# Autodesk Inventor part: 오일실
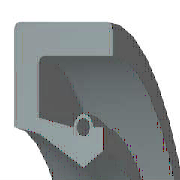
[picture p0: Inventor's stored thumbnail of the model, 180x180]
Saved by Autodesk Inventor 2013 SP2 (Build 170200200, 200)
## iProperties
IsCustomPart: 1
Company: 한국ATC센터
Created: 2014-10
Part Number: 오일실
Material: 고무
Description: 오일-실
Document SubType Name: Modeling
Standard: KS B 2804
Designer: 한국ATC센터
Standards Organization: KS
Language: ko-KR
Size Designation: S - 25 40 8
Categories: <MemberInstance><Categories><Category DisplayName="샤프트 부품" InternalName="7f7aeb1f-a693-4053-b835-cee3144e0d98" Mnemonic="SHFT"><Category DisplayName="실링" Intern
Density: 0.93 g/cm^3
Mass: 2.48215 g
Surface Area: 40.3381 cm^2
Volume: 2.66898 cm^3
Author: KYOUNG IL JANG
Revision Number: 1
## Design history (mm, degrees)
revolve "본체" stored, may be unused: angle "d17" = 90 deg
revolve "스프링1" stored, may be unused: angle "d18" = 90 deg
body "Solid1"
sketch "스케치1"
  geometry: L1 (0, 20)-(8, 20); L2 (8, 20)-(8, 18.75); L3 (8, 18.75)-(1.75, 18.75); L4 (0, 20)-(0, 14.6); L5 (0, 14.6)-(1.75, 14.25); L6 (1.75, 14.25)-(4.9, 12.5); L7 (4.9, 12.5)-(0, 12.5); L8 (6.3, 13.375)-(6.3, 14.6); L9 (0, 0)-(9.586, 0) reference; L10 (4.9, 12.5)-(6.3, 13.375); L11 (0, 18)-(0, -3) reference; L12 (-1.917, 0)-(11.503, 0) reference; L13 (4.2, 14.6)-(1.75, 15.09); L14 (1.75, 15.09)-(1.75, 18.75); L15 (6.3, 14.6)-(5.6, 14.6); C1 r 0.455 at (4.9, 14.6); A1 r 0.7 centre (4.9, 14.6) between (5.6, 14.6) and (4.2, 14.6)
  constraints: 26 end point, 5 horizontal alignment, 4 perpendicular, 2 centre point, 2 collinear, 2 horizontal, 2 parallel, 2 point on circle, 2 point on line, 2 vertical alignment, 1 coincident
  dimensions: "d0" = 40 diameter of L1 L9 (= SD2); "d1" = 26.75 diameter of L8.start L9 (= ABDM); "d2" = 1.25 distance of L1.end L2.end (computed from SD); "d3" = 0.91 diameter of C1 (= SPDI); "d4" = 1.4 diameter of A1 (= SPDA); "d5" = 25 diameter of L6.end L9 (= NND); "d6" = 28.5 diameter of L5.end L9 (= TKDM); "d7" = 29.2 diameter of L4.end L9 (= HLDM); "d8" = 4.9 distance from line of C1.centre L4 (= SPDST); "d9" = 6.3 distance between parallel lines of L8 L4 (= SDI); "d10" = 8 distance between parallel lines of L2 L4 (= SWDT); "d12" = 1.75 distance between parallel lines of L14 L4 (= SD)
fillet "모깎기1" dims "d11" = 0.3 (= RR)
other parameters: "SD2" = 40 [user parameter; used in 1 equation term], "SWDT" = 8 [user parameter; used in 1 equation term], "RR" = 0.3 [user parameter; used in 1 equation term], "SD" = 1.75 [user parameter; used in 2 equation terms], "NND" = 25 [user parameter; used in 1 equation term], "SPDA" = 1.4 [user parameter; used in 1 equation term], "SPDI" = 0.91 [user parameter; used in 1 equation term], "TKDM" = 28.5 [user parameter; used in 1 equation term], "HLDM" = 29.2 [user parameter; used in 1 equation term], "ABDM" = 26.75 [user parameter; used in 1 equation term], "SDI" = 6.3 [user parameter; used in 1 equation term], "SPDST" = 4.9 [user parameter; used in 1 equation term], "d13" = 0, "d14" = 0, "d15" = 0, "LAB" = 0.35 [user parameter]
